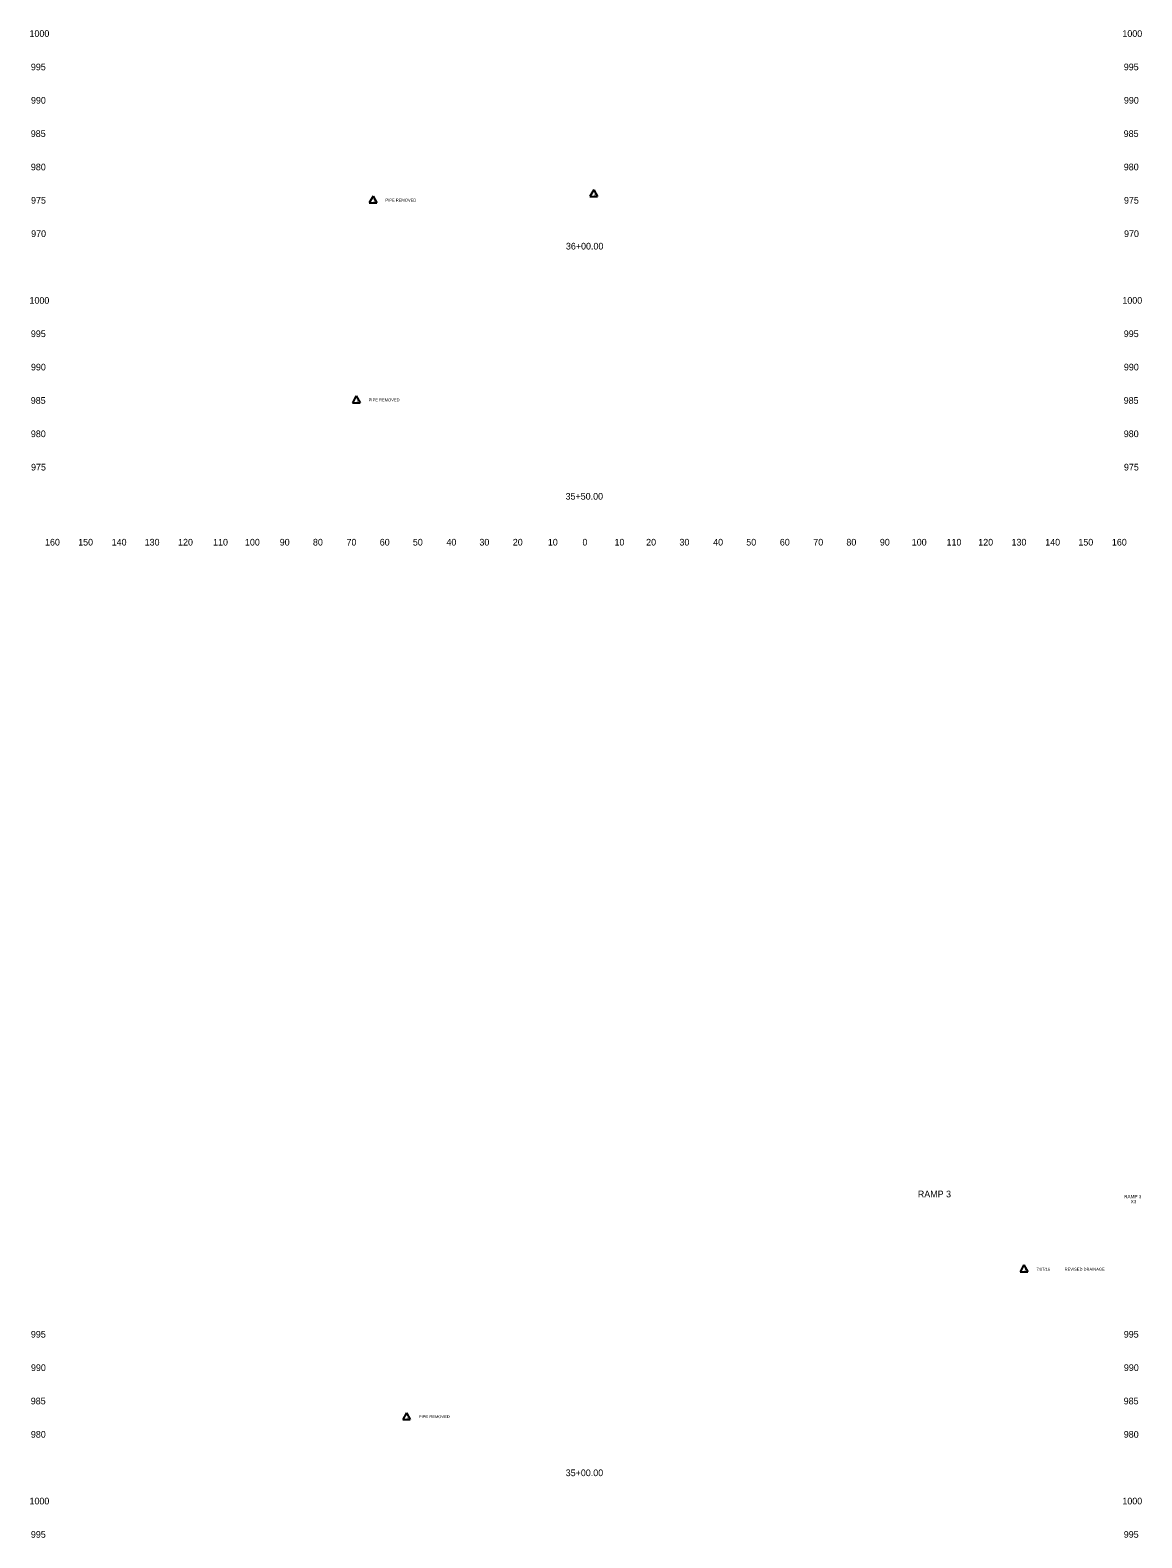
# Model space of a CAD drawing. Extents: x 4994 to 5843, y 4997 to 8804.
# Drawn here: x 4993.6 to 5327.1, y 5900 to 6352 of the extents above; entities that cross this region are included whole.
import ezdxf

# ---------------------------------------------------------------- set-up
doc = ezdxf.new("R2010")
doc.units = 0
for name, color, linetype in [('RD_SHT_ID', 7, 'Continuous'), ('RD_SHT_TX', 7, 'Continuous'), ('RD_XS_TX_Offset', 7, 'Continuous'), ('RD_XS_TX_Station', 7, 'Continuous')]:
    doc.layers.add(name, color=color, linetype=linetype)

msp = doc.modelspace()

# ---------------------------------------------------------------- linework, layer by layer
at = {"layer": 'RD_SHT_TX'}
for p, q in [((5096.5, 6302.24), (5095.36, 6300.21)), ((5096.5, 6302.24), (5097.63, 6300.21)), ((5162.7, 6304.2), (5161.56, 6302.17)), ((5161.56, 6302.17), (5163.84, 6302.17)), ((5162.7, 6304.2), (5163.84, 6302.17)), ((5095.36, 6300.21), (5097.63, 6300.21)), ((5091.46, 6242.34), (5090.32, 6240.31)), ((5090.32, 6240.31), (5092.6, 6240.31)), ((5091.46, 6242.34), (5092.6, 6240.31)), ((5291.7, 5981.8), (5290.56, 5979.77)), ((5291.7, 5981.8), (5292.84, 5979.77)), ((5290.56, 5979.77), (5292.84, 5979.77)), ((5106.52, 5937.47), (5105.38, 5935.44)), ((5106.52, 5937.47), (5107.66, 5935.44)), ((5105.38, 5935.44), (5107.66, 5935.44))]:
    msp.add_line(p, q, dxfattribs=at)

# ---------------------------------------------------------------- texts
at = {"layer": 'RD_SHT_ID'}
for s, height, p in [('RAMP 3', 2, (5259.89, 6002.06)), ('RAMP 3', 1, (5321.78, 6001.8)), ('X3', 1, (5323.74, 6000.3))]:
    msp.add_text(s, height=height, dxfattribs=at).set_placement(p)
at = {"layer": 'RD_SHT_TX'}
for s, p in [('1', (5162.7, 6302.5)), ('1', (5096.5, 6300.54)), ('PIPE REMOVED', (5100.21, 6300.63)), ('1', (5091.46, 6240.64)), ('PIPE REMOVED', (5095.18, 6240.73)), ('1', (5291.7, 5980.1)), ('7/07/16', (5295.48, 5980.06)), ('REVISED DRAINAGE', (5303.93, 5980.06)), ('1', (5106.52, 5935.77)), ('PIPE REMOVED', (5110.24, 5935.86))]:
    msp.add_text(s, height=0.88, dxfattribs=at).set_placement(p)
at = {"layer": 'RD_XS_TX_Offset'}
for s, p in [('1000', (4993.44, 6350)), ('1000', (5321.24, 6350)), ('995', (4993.86, 6340)), ('995', (5321.66, 6340)), ('990', (4993.89, 6330)), ('990', (5321.69, 6330)), ('985', (4993.83, 6320)), ('985', (5321.63, 6320)), ('980', (4993.86, 6310)), ('980', (5321.66, 6310)), ('975', (4993.91, 6300)), ('975', (5321.71, 6300)), ('970', (4993.94, 6290)), ('970', (5321.74, 6290)), ('1000', (4993.44, 6270)), ('1000', (5321.24, 6270)), ('995', (4993.86, 6260)), ('995', (5321.66, 6260)), ('990', (4993.89, 6250)), ('990', (5321.69, 6250)), ('985', (4993.83, 6240)), ('985', (5321.63, 6240)), ('980', (4993.86, 6230)), ('980', (5321.66, 6230)), ('975', (4993.91, 6220)), ('975', (5321.71, 6220)), ('160', (4998.1, 6197.5)), ('150', (5008.04, 6197.5)), ('140', (5018.1, 6197.5)), ('130', (5027.99, 6197.5)), ('120', (5038.01, 6197.5)), ('110', (5048.51, 6197.5)), ('100', (5058.07, 6197.5)), ('90', (5068.5, 6197.5)), ('80', (5078.46, 6197.5)), ('70', (5088.54, 6197.5)), ('60', (5098.5, 6197.5)), ('50', (5108.43, 6197.5)), ('40', (5118.5, 6197.5)), ('30', (5128.39, 6197.5)), ('20', (5138.4, 6197.5)), ('10', (5148.91, 6197.5)), ('0', (5159.3, 6197.5)), ('0', (5159.3, 6197.5)), ('10', (5168.91, 6197.5)), ('20', (5178.4, 6197.5)), ('30', (5188.39, 6197.5)), ('40', (5198.5, 6197.5)), ('50', (5208.43, 6197.5)), ('60', (5218.5, 6197.5)), ('70', (5228.54, 6197.5)), ('80', (5238.46, 6197.5)), ('90', (5248.5, 6197.5)), ('100', (5258.07, 6197.5)), ('110', (5268.51, 6197.5)), ('120', (5278.01, 6197.5)), ('130', (5287.99, 6197.5)), ('140', (5298.1, 6197.5)), ('150', (5308.04, 6197.5)), ('160', (5318.1, 6197.5)), ('995', (4993.86, 5960)), ('995', (5321.66, 5960)), ('990', (4993.89, 5950)), ('990', (5321.69, 5950)), ('985', (4993.83, 5940)), ('985', (5321.63, 5940)), ('980', (4993.86, 5930)), ('980', (5321.66, 5930)), ('1000', (4993.44, 5910)), ('1000', (5321.24, 5910)), ('995', (4993.86, 5900)), ('995', (5321.66, 5900))]:
    msp.add_text(s, height=2, dxfattribs=at).set_placement(p)
at = {"layer": 'RD_XS_TX_Station'}
for s, p in [('36+00.00', (5154.34, 6286.26)), ('35+50.00', (5154.24, 6211.26)), ('35+00.00', (5154.28, 5918.47))]:
    msp.add_text(s, height=2, dxfattribs=at).set_placement(p)

doc.saveas('drawing.dxf')
